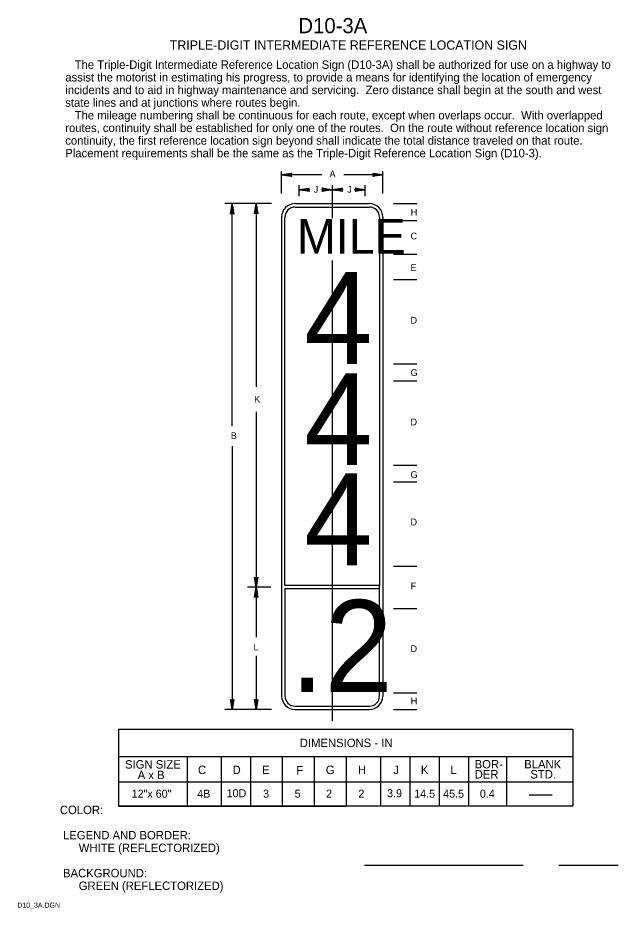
# Model space of a CAD drawing. Extents: x 0.013 to 0.191, y 0.004 to 0.268.
import ezdxf

# ---------------------------------------------------------------- set-up
doc = ezdxf.new("R2010")
doc.units = 0
doc.layers.add('1', color=7, linetype='Continuous')
doc.layers.add('3', color=7, linetype='Continuous')

# ---------------------------------------------------------------- blocks, each defined once
blk = doc.blocks.new('RARROW')
at = {"layer": '3'}
for p, q in [((-2.156, 0.285), (-2.2665, 0.384625)), ((-2.2665, 0.384625), (0, 0)), ((0, 0), (-2.2665, -0.379125)), ((-2.156, 0.285), (-2.075625, 0.12075)), ((0, 0), (-2.156, 0.285)), ((-2.14975, -0.2705), (0, 0)), ((-2.075625, 0.12075), (0, 0)), ((0, 0), (-2.074, -0.108)), ((-2.2665, -0.379125), (-2.14975, -0.2705)), ((-2.074, -0.108), (-2.14975, -0.2705))]:
    blk.add_line(p, q, dxfattribs=at)

msp = doc.modelspace()

# ---------------------------------------------------------------- linework, layer by layer
at = {"layer": '1'}
for p, q in [((0.11983, 0.09888), (0.11983, 0.09988)), ((0.16415, 0.03785), (0.17103, 0.03785)), ((0.11544, 0.01695), (0.16242, 0.01695)), ((0.17295, 0.01695), (0.19056, 0.01695))]:
    msp.add_line(p, q, dxfattribs=at)
at = {"layer": '3'}
for p, q in [((0.09083, 0.21616), (0.09083, 0.22277)), ((0.12083, 0.21616), (0.12083, 0.22277)), ((0.10273, 0.22169), (0.09083, 0.22169)), ((0.12083, 0.22169), (0.10928, 0.22169)), ((0.09603, 0.21539), (0.09603, 0.21864)), ((0.09922, 0.21727), (0.09603, 0.21727)), ((0.10908, 0.21727), (0.10266, 0.21727)), ((0.10583, 0.21859), (0.10583, 0.21533)), ((0.11563, 0.21727), (0.11237, 0.21727)), ((0.11563, 0.21539), (0.11563, 0.21864)), ((0.10583, 0.21533), (0.10583, 0.20887)), ((0.08781, 0.21313), (0.07398, 0.21313)), ((0.07614, 0.14719), (0.07614, 0.21313)), ((0.08331, 0.21313), (0.08331, 0.15884)), ((0.09483, 0.21313), (0.11683, 0.21313)), ((0.09483, 0.21313), (0.11683, 0.21313)), ((0.09483, 0.21211), (0.11683, 0.21211)), ((0.12402, 0.21313), (0.1309, 0.21313)), ((0.09083, 0.20913), (0.09083, 0.06713)), ((0.09183, 0.09988), (0.09183, 0.20913)), ((0.11983, 0.20913), (0.11983, 0.09988)), ((0.12083, 0.20913), (0.12083, 0.06713)), ((0.12402, 0.20813), (0.1309, 0.20813)), ((0.10583, 0.19624), (0.10583, 0.05977)), ((0.12402, 0.19813), (0.1309, 0.19813)), ((0.12402, 0.19063), (0.1309, 0.19063)), ((0.12402, 0.16563), (0.1309, 0.16563)), ((0.12402, 0.16063), (0.1309, 0.16063)), ((0.08331, 0.1514), (0.08331, 0.09938)), ((0.07614, 0.14125), (0.07614, 0.06313)), ((0.12402, 0.13563), (0.1309, 0.13563)), ((0.12402, 0.13063), (0.1309, 0.13063)), ((0.12402, 0.10563), (0.1309, 0.10563)), ((0.08764, 0.09938), (0.08077, 0.09938)), ((0.08331, 0.09938), (0.08331, 0.08459)), ((0.11983, 0.09988), (0.09183, 0.09988)), ((0.11983, 0.09888), (0.09183, 0.09888)), ((0.09183, 0.09888), (0.09183, 0.06713)), ((0.11983, 0.06713), (0.11983, 0.09888)), ((0.12402, 0.09313), (0.1309, 0.09313)), ((0.08331, 0.07905), (0.08331, 0.06313)), ((0.12402, 0.06813), (0.1309, 0.06813)), ((0.09483, 0.06413), (0.11683, 0.06413)), ((0.08781, 0.06313), (0.07398, 0.06313)), ((0.08764, 0.06313), (0.08077, 0.06313)), ((0.08764, 0.06313), (0.08077, 0.06313)), ((0.09483, 0.06313), (0.11683, 0.06313)), ((0.12402, 0.06313), (0.1309, 0.06313)), ((0.04253, 0.05728), (0.17715, 0.05728)), ((0.04253, 0.05728), (0.04253, 0.03445)), ((0.17715, 0.05728), (0.17715, 0.03445)), ((0.17715, 0.04915), (0.04253, 0.04915)), ((0.06283, 0.049), (0.06283, 0.03445)), ((0.07294, 0.04915), (0.07294, 0.03445)), ((0.08163, 0.049), (0.08163, 0.03445)), ((0.09103, 0.049), (0.09103, 0.03445)), ((0.10043, 0.049), (0.10043, 0.03445)), ((0.11, 0.04915), (0.11, 0.03445)), ((0.12011, 0.04915), (0.12011, 0.03445)), ((0.1288, 0.049), (0.1288, 0.03445)), ((0.13749, 0.04915), (0.13749, 0.03445)), ((0.14618, 0.049), (0.14618, 0.03445)), ((0.15746, 0.049), (0.15746, 0.03445)), ((0.04253, 0.04174), (0.17715, 0.04174)), ((0.17715, 0.03445), (0.04253, 0.03445)), ((0.04253, 0.03445), (0.11, 0.03445)), ((0.11, 0.03445), (0.04277, 0.03445))]:
    msp.add_line(p, q, dxfattribs=at)
for centre, radius, start, end in [((0.09483, 0.20913), 0.004, 90, 180), ((0.09483, 0.20913), 0.003, 90, 180), ((0.11683, 0.20913), 0.004, 360, 90), ((0.11683, 0.20913), 0.003, 360, 90), ((0.09483, 0.06713), 0.004, 180, 270), ((0.09483, 0.06713), 0.003, 180, 270), ((0.11683, 0.06713), 0.003, 270, 0), ((0.11683, 0.06713), 0.004, 270, 0)]:
    msp.add_arc(centre, radius, start, end, dxfattribs=at)

# ---------------------------------------------------------------- block references
at = {"layer": '3', "xscale": 0.0013236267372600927, "yscale": 0.001309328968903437}
for p, rotation in [((0.09083, 0.22169), 180), ((0.09603, 0.21727), 180), ((0.10583, 0.21727), 180), ((0.07614, 0.21305), 90), ((0.08331, 0.21313), 90), ((0.08331, 0.09938), -90), ((0.08331, 0.09938), 90), ((0.07614, 0.06313), -90), ((0.08331, 0.06313), -90)]:
    msp.add_blockref('RARROW', p, dxfattribs=dict(at, rotation=rotation))
for p in [(0.12083, 0.22169), (0.10583, 0.21727), (0.11563, 0.21727)]:
    msp.add_blockref('RARROW', p, dxfattribs=at)

# ---------------------------------------------------------------- texts
at = {"layer": '1'}
for s, height, p in [('D10-3A', 0.0045, (0.09581, 0.26366)), ('TRIPLE-DIGIT INTERMEDIATE REFERENCE LOCATION SIGN', 0.0027503, (0.05769, 0.25877)), ('COLOR:', 0.0025, (0.02513, 0.03213)), (' LEGEND AND BORDER:', 0.0024998, (0.02513, 0.02463)), ('      WHITE (REFLECTORIZED)', 0.0024998, (0.02513, 0.02088)), (' BACKGROUND:', 0.0024998, (0.02513, 0.01338)), ('      GREEN (REFLECTORIZED)', 0.0024998, (0.02513, 0.00963)), ('D10_3A.DGN', 0.0015, (0.0125, 0.00438))]:
    msp.add_text(s, height=height, dxfattribs=at).set_placement(p)
at = {"layer": '3'}
for s, height, p in [('   The Triple-Digit Intermediate Reference Location Sign (D10-3A) shall be authorized for use on a highway to', 0.00249975, (0.02672, 0.2531)), ('assist the motorist in estimating his progress, to provide a means for identifying the location of emergency', 0.00249975, (0.02672, 0.24935)), ('incidents and to aid in highway maintenance and servicing.  Zero distance shall begin at the south and west', 0.00249975, (0.02672, 0.2456)), ('state lines and at junctions where routes begin. ', 0.0024998, (0.02672, 0.24185)), ('   The mileage numbering shall be continuous for each route, except when overlaps occur.  With overlapped', 0.00249975, (0.02672, 0.2381)), ('routes, continuity shall be established for only one of the routes.  On the route without reference location sign', 0.00249975, (0.02672, 0.23435)), ('continuity, the first reference location sign beyond shall indicate the total distance traveled on that route.  ', 0.00249975, (0.02672, 0.2306)), ('Placement requirements shall be the same as the Triple-Digit Reference Location Sign (D10-3).', 0.0024998, (0.02672, 0.22686)), ('A', 0.002, (0.10503, 0.22095)), ('J', 0.002, (0.10034, 0.21637)), ('J', 0.002, (0.11026, 0.21637)), ('C', 0.002, (0.12904, 0.20254)), ('E', 0.002, (0.12905, 0.19313)), ('G', 0.002, (0.12904, 0.16201)), ('K', 0.002, (0.08272, 0.15414)), ('D', 0.002, (0.12904, 0.14742)), ('B', 0.002, (0.07577, 0.14331)), ('G', 0.002, (0.12904, 0.13179)), ('D', 0.002, (0.12904, 0.11772)), ('F', 0.002, (0.12909, 0.09879)), ('L', 0.002, (0.08252, 0.08069)), ('DIMENSIONS - IN', 0.0024998, (0.09621, 0.052)), ('SIGN SIZE', 0.0025, (0.04443, 0.04562)), ('BOR-', 0.0025, (0.14803, 0.04568)), ('BLANK', 0.0025, (0.16273, 0.04569)), ('A x B', 0.0025, (0.04818, 0.0425)), ('C', 0.0025, (0.06605, 0.044)), ('D', 0.0025, (0.0763, 0.044)), ('E', 0.0025, (0.08505, 0.044)), ('F', 0.0025, (0.09518, 0.04387)), ('G', 0.0025, (0.10393, 0.044)), ('H', 0.0025, (0.11345, 0.044)), ('J', 0.0025, (0.12393, 0.044)), ('K', 0.0025, (0.13211, 0.044)), ('DER', 0.0025, (0.14803, 0.04268)), ('STD.', 0.0025, (0.16453, 0.04269)), ('12"x 60"', 0.002375, (0.04639, 0.037)), ('4B', 0.002375, (0.06582, 0.037)), ('10D', 0.002375, (0.07455, 0.03713)), ('3', 0.00238, (0.08536, 0.037)), ('5', 0.00238, (0.0947, 0.037)), ('2', 0.00238, (0.104, 0.037)), ('2', 0.00238, (0.11357, 0.037)), ('3.9', 0.002375, (0.12209, 0.03713)), ('14.5', 0.002375, (0.13013, 0.037)), ('45.5', 0.002375, (0.1387, 0.037)), ('0.4', 0.002375, (0.14958, 0.037))]:
    msp.add_text(s, height=height, dxfattribs=at).set_placement(p)
for s, height, p in [('H', 0.002, (0.1291, 0.20959)), ('MILE', 0.010321, (0.09538, 0.19828)), ('4', 0.02726, (0.09752, 0.1656)), ('D', 0.002, (0.12904, 0.17757)), ('4', 0.02726, (0.09752, 0.1356)), ('4', 0.02726, (0.09752, 0.10589)), ('.2', 0.027261, (0.09337, 0.06835)), ('D', 0.002, (0.12904, 0.08017)), ('H', 0.002, (0.1291, 0.06467)), ('L', 0.0025, (0.14082, 0.044))]:
    msp.add_text(s, height=height, rotation=360, dxfattribs=at).set_placement(p)

doc.saveas('drawing.dxf')
